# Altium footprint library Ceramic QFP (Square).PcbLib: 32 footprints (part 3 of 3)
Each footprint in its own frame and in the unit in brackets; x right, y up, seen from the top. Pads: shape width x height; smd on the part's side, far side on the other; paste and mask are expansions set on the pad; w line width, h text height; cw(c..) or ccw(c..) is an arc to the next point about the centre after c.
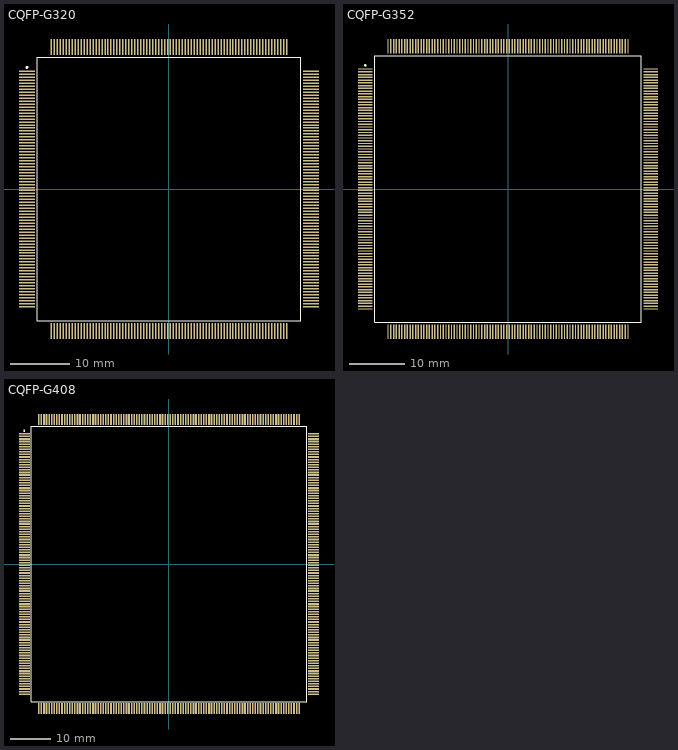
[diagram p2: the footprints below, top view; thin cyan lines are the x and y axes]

## CQFP-G320 [mm]
pads (320):
  rect 2.65x0.25 smd: 1(-23.875,19.75) 2(-23.875,19.25) 3(-23.875,18.75) 4(-23.875,18.25) 5(-23.875,17.75) 6(-23.875,17.25) 7(-23.875,16.75) 8(-23.875,16.25) 9(-23.875,15.75) 10(-23.875,15.25) 11(-23.875,14.75) 12(-23.875,14.25) 13(-23.875,13.75) 14(-23.875,13.25) 15(-23.875,12.75) 16(-23.875,12.25) 17(-23.875,11.75) 18(-23.875,11.25) 19(-23.875,10.75) 20(-23.875,10.25) 21(-23.875,9.75) 22(-23.875,9.25) 23(-23.875,8.75) 24(-23.875,8.25) 25(-23.875,7.75) 26(-23.875,7.25) 27(-23.875,6.75) 28(-23.875,6.25) 29(-23.875,5.75) 30(-23.875,5.25) 31(-23.875,4.75) 32(-23.875,4.25) 33(-23.875,3.75) 34(-23.875,3.25) 35(-23.875,2.75) 36(-23.875,2.25) 37(-23.875,1.75) 38(-23.875,1.25) 39(-23.875,0.75) 40(-23.875,0.25) 41(-23.875,-0.25) 42(-23.875,-0.75) 43(-23.875,-1.25) 44(-23.875,-1.75) 45(-23.875,-2.25) 46(-23.875,-2.75) 47(-23.875,-3.25) 48(-23.875,-3.75) 49(-23.875,-4.25) 50(-23.875,-4.75) 51(-23.875,-5.25) 52(-23.875,-5.75) 53(-23.875,-6.25) 54(-23.875,-6.75) 55(-23.875,-7.25) 56(-23.875,-7.75) 57(-23.875,-8.25) 58(-23.875,-8.75) 59(-23.875,-9.25) 60(-23.875,-9.75) 61(-23.875,-10.25) 62(-23.875,-10.75) 63(-23.875,-11.25) 64(-23.875,-11.75) 65(-23.875,-12.25) 66(-23.875,-12.75) 67(-23.875,-13.25) 68(-23.875,-13.75) 69(-23.875,-14.25) 70(-23.875,-14.75) 71(-23.875,-15.25) 72(-23.875,-15.75) 73(-23.875,-16.25) 74(-23.875,-16.75) 75(-23.875,-17.25) 76(-23.875,-17.75) 77(-23.875,-18.25) 78(-23.875,-18.75) 79(-23.875,-19.25) 80(-23.875,-19.75) 161(23.875,-19.75) 162(23.875,-19.25) 163(23.875,-18.75) 164(23.875,-18.25) 165(23.875,-17.75) 166(23.875,-17.25) 167(23.875,-16.75) 168(23.875,-16.25) 169(23.875,-15.75) 170(23.875,-15.25) 171(23.875,-14.75) 172(23.875,-14.25) 173(23.875,-13.75) 174(23.875,-13.25) 175(23.875,-12.75) 176(23.875,-12.25) 177(23.875,-11.75) 178(23.875,-11.25) 179(23.875,-10.75) 180(23.875,-10.25) 181(23.875,-9.75) 182(23.875,-9.25) 183(23.875,-8.75) 184(23.875,-8.25) 185(23.875,-7.75) 186(23.875,-7.25) 187(23.875,-6.75) 188(23.875,-6.25) 189(23.875,-5.75) 190(23.875,-5.25) 191(23.875,-4.75) 192(23.875,-4.25) 193(23.875,-3.75) 194(23.875,-3.25) 195(23.875,-2.75) 196(23.875,-2.25) 197(23.875,-1.75) 198(23.875,-1.25) 199(23.875,-0.75) 200(23.875,-0.25) 201(23.875,0.25) 202(23.875,0.75) 203(23.875,1.25) 204(23.875,1.75) 205(23.875,2.25) 206(23.875,2.75) 207(23.875,3.25) 208(23.875,3.75) 209(23.875,4.25) 210(23.875,4.75) 211(23.875,5.25) 212(23.875,5.75) 213(23.875,6.25) 214(23.875,6.75) 215(23.875,7.25) 216(23.875,7.75) 217(23.875,8.25) 218(23.875,8.75) 219(23.875,9.25) 220(23.875,9.75) 221(23.875,10.25) 222(23.875,10.75) 223(23.875,11.25) 224(23.875,11.75) 225(23.875,12.25) 226(23.875,12.75) 227(23.875,13.25) 228(23.875,13.75) 229(23.875,14.25) 230(23.875,14.75) 231(23.875,15.25) 232(23.875,15.75) 233(23.875,16.25) 234(23.875,16.75) 235(23.875,17.25) 236(23.875,17.75) 237(23.875,18.25) 238(23.875,18.75) 239(23.875,19.25) 240(23.875,19.75)
  rect 0.25x2.65 smd: 81(-19.75,-23.875) 82(-19.25,-23.875) 83(-18.75,-23.875) 84(-18.25,-23.875) 85(-17.75,-23.875) 86(-17.25,-23.875) 87(-16.75,-23.875) 88(-16.25,-23.875) 89(-15.75,-23.875) 90(-15.25,-23.875) 91(-14.75,-23.875) 92(-14.25,-23.875) 93(-13.75,-23.875) 94(-13.25,-23.875) 95(-12.75,-23.875) 96(-12.25,-23.875) 97(-11.75,-23.875) 98(-11.25,-23.875) 99(-10.75,-23.875) 100(-10.25,-23.875) 101(-9.75,-23.875) 102(-9.25,-23.875) 103(-8.75,-23.875) 104(-8.25,-23.875) 105(-7.75,-23.875) 106(-7.25,-23.875) 107(-6.75,-23.875) 108(-6.25,-23.875) 109(-5.75,-23.875) 110(-5.25,-23.875) 111(-4.75,-23.875) 112(-4.25,-23.875) 113(-3.75,-23.875) 114(-3.25,-23.875) 115(-2.75,-23.875) 116(-2.25,-23.875) 117(-1.75,-23.875) 118(-1.25,-23.875) 119(-0.75,-23.875) 120(-0.25,-23.875) 121(0.25,-23.875) 122(0.75,-23.875) 123(1.25,-23.875) 124(1.75,-23.875) 125(2.25,-23.875) 126(2.75,-23.875) 127(3.25,-23.875) 128(3.75,-23.875) 129(4.25,-23.875) 130(4.75,-23.875) 131(5.25,-23.875) 132(5.75,-23.875) 133(6.25,-23.875) 134(6.75,-23.875) 135(7.25,-23.875) 136(7.75,-23.875) 137(8.25,-23.875) 138(8.75,-23.875) 139(9.25,-23.875) 140(9.75,-23.875) 141(10.25,-23.875) 142(10.75,-23.875) 143(11.25,-23.875) 144(11.75,-23.875) 145(12.25,-23.875) 146(12.75,-23.875) 147(13.25,-23.875) 148(13.75,-23.875) 149(14.25,-23.875) 150(14.75,-23.875) 151(15.25,-23.875) 152(15.75,-23.875) 153(16.25,-23.875) 154(16.75,-23.875) 155(17.25,-23.875) 156(17.75,-23.875) 157(18.25,-23.875) 158(18.75,-23.875) 159(19.25,-23.875) 160(19.75,-23.875) 241(19.75,23.875) 242(19.25,23.875) 243(18.75,23.875) 244(18.25,23.875) 245(17.75,23.875) 246(17.25,23.875) 247(16.75,23.875) 248(16.25,23.875) 249(15.75,23.875) 250(15.25,23.875) 251(14.75,23.875) 252(14.25,23.875) 253(13.75,23.875) 254(13.25,23.875) 255(12.75,23.875) 256(12.25,23.875) 257(11.75,23.875) 258(11.25,23.875) 259(10.75,23.875) 260(10.25,23.875) 261(9.75,23.875) 262(9.25,23.875) 263(8.75,23.875) 264(8.25,23.875) 265(7.75,23.875) 266(7.25,23.875) 267(6.75,23.875) 268(6.25,23.875) 269(5.75,23.875) 270(5.25,23.875) 271(4.75,23.875) 272(4.25,23.875) 273(3.75,23.875) 274(3.25,23.875) 275(2.75,23.875) 276(2.25,23.875) 277(1.75,23.875) 278(1.25,23.875) 279(0.75,23.875) 280(0.25,23.875) 281(-0.25,23.875) 282(-0.75,23.875) 283(-1.25,23.875) 284(-1.75,23.875) 285(-2.25,23.875) 286(-2.75,23.875) 287(-3.25,23.875) 288(-3.75,23.875) 289(-4.25,23.875) 290(-4.75,23.875) 291(-5.25,23.875) 292(-5.75,23.875) 293(-6.25,23.875) 294(-6.75,23.875) 295(-7.25,23.875) 296(-7.75,23.875) 297(-8.25,23.875) 298(-8.75,23.875) 299(-9.25,23.875) 300(-9.75,23.875) 301(-10.25,23.875) 302(-10.75,23.875) 303(-11.25,23.875) 304(-11.75,23.875) 305(-12.25,23.875) 306(-12.75,23.875) 307(-13.25,23.875) 308(-13.75,23.875) 309(-14.25,23.875) 310(-14.75,23.875) 311(-15.25,23.875) 312(-15.75,23.875) 313(-16.25,23.875) 314(-16.75,23.875) 315(-17.25,23.875) 316(-17.75,23.875) 317(-18.25,23.875) 318(-18.75,23.875) 319(-19.25,23.875) 320(-19.75,23.875)
Top Overlay:
  circle w0.25: c-23.875,20.425 r0.125
  lines w0.2: -22.15,-22.15 -22.15,22.15 22.15,22.15 22.15,-22.15 -22.15,-22.15

## CQFP-G352 [mm]
pads (352):
  rect 2.65x0.25 smd: 1(-25.875,21.75) 2(-25.875,21.25) 3(-25.875,20.75) 4(-25.875,20.25) 5(-25.875,19.75) 6(-25.875,19.25) 7(-25.875,18.75) 8(-25.875,18.25) 9(-25.875,17.75) 10(-25.875,17.25) 11(-25.875,16.75) 12(-25.875,16.25) 13(-25.875,15.75) 14(-25.875,15.25) 15(-25.875,14.75) 16(-25.875,14.25) 17(-25.875,13.75) 18(-25.875,13.25) 19(-25.875,12.75) 20(-25.875,12.25) 21(-25.875,11.75) 22(-25.875,11.25) 23(-25.875,10.75) 24(-25.875,10.25) 25(-25.875,9.75) 26(-25.875,9.25) 27(-25.875,8.75) 28(-25.875,8.25) 29(-25.875,7.75) 30(-25.875,7.25) 31(-25.875,6.75) 32(-25.875,6.25) 33(-25.875,5.75) 34(-25.875,5.25) 35(-25.875,4.75) 36(-25.875,4.25) 37(-25.875,3.75) 38(-25.875,3.25) 39(-25.875,2.75) 40(-25.875,2.25) 41(-25.875,1.75) 42(-25.875,1.25) 43(-25.875,0.75) 44(-25.875,0.25) 45(-25.875,-0.25) 46(-25.875,-0.75) 47(-25.875,-1.25) 48(-25.875,-1.75) 49(-25.875,-2.25) 50(-25.875,-2.75) 51(-25.875,-3.25) 52(-25.875,-3.75) 53(-25.875,-4.25) 54(-25.875,-4.75) 55(-25.875,-5.25) 56(-25.875,-5.75) 57(-25.875,-6.25) 58(-25.875,-6.75) 59(-25.875,-7.25) 60(-25.875,-7.75) 61(-25.875,-8.25) 62(-25.875,-8.75) 63(-25.875,-9.25) 64(-25.875,-9.75) 65(-25.875,-10.25) 66(-25.875,-10.75) 67(-25.875,-11.25) 68(-25.875,-11.75) 69(-25.875,-12.25) 70(-25.875,-12.75) 71(-25.875,-13.25) 72(-25.875,-13.75) 73(-25.875,-14.25) 74(-25.875,-14.75) 75(-25.875,-15.25) 76(-25.875,-15.75) 77(-25.875,-16.25) 78(-25.875,-16.75) 79(-25.875,-17.25) 80(-25.875,-17.75) 81(-25.875,-18.25) 82(-25.875,-18.75) 83(-25.875,-19.25) 84(-25.875,-19.75) 85(-25.875,-20.25) 86(-25.875,-20.75) 87(-25.875,-21.25) 88(-25.875,-21.75) 177(25.875,-21.75) 178(25.875,-21.25) 179(25.875,-20.75) 180(25.875,-20.25) 181(25.875,-19.75) 182(25.875,-19.25) 183(25.875,-18.75) 184(25.875,-18.25) 185(25.875,-17.75) 186(25.875,-17.25) 187(25.875,-16.75) 188(25.875,-16.25) 189(25.875,-15.75) 190(25.875,-15.25) 191(25.875,-14.75) 192(25.875,-14.25) 193(25.875,-13.75) 194(25.875,-13.25) 195(25.875,-12.75) 196(25.875,-12.25) 197(25.875,-11.75) 198(25.875,-11.25) 199(25.875,-10.75) 200(25.875,-10.25) 201(25.875,-9.75) 202(25.875,-9.25) 203(25.875,-8.75) 204(25.875,-8.25) 205(25.875,-7.75) 206(25.875,-7.25) 207(25.875,-6.75) 208(25.875,-6.25) 209(25.875,-5.75) 210(25.875,-5.25) 211(25.875,-4.75) 212(25.875,-4.25) 213(25.875,-3.75) 214(25.875,-3.25) 215(25.875,-2.75) 216(25.875,-2.25) 217(25.875,-1.75) 218(25.875,-1.25) 219(25.875,-0.75) 220(25.875,-0.25) 221(25.875,0.25) 222(25.875,0.75) 223(25.875,1.25) 224(25.875,1.75) 225(25.875,2.25) 226(25.875,2.75) 227(25.875,3.25) 228(25.875,3.75) 229(25.875,4.25) 230(25.875,4.75) 231(25.875,5.25) 232(25.875,5.75) 233(25.875,6.25) 234(25.875,6.75) 235(25.875,7.25) 236(25.875,7.75) 237(25.875,8.25) 238(25.875,8.75) 239(25.875,9.25) 240(25.875,9.75) 241(25.875,10.25) 242(25.875,10.75) 243(25.875,11.25) 244(25.875,11.75) 245(25.875,12.25) 246(25.875,12.75) 247(25.875,13.25) 248(25.875,13.75) 249(25.875,14.25) 250(25.875,14.75) 251(25.875,15.25) 252(25.875,15.75) 253(25.875,16.25) 254(25.875,16.75) 255(25.875,17.25) 256(25.875,17.75) 257(25.875,18.25) 258(25.875,18.75) 259(25.875,19.25) 260(25.875,19.75) 261(25.875,20.25) 262(25.875,20.75) 263(25.875,21.25) 264(25.875,21.75)
  rect 0.25x2.65 smd: 89(-21.75,-25.875) 90(-21.25,-25.875) 91(-20.75,-25.875) 92(-20.25,-25.875) 93(-19.75,-25.875) 94(-19.25,-25.875) 95(-18.75,-25.875) 96(-18.25,-25.875) 97(-17.75,-25.875) 98(-17.25,-25.875) 99(-16.75,-25.875) 100(-16.25,-25.875) 101(-15.75,-25.875) 102(-15.25,-25.875) 103(-14.75,-25.875) 104(-14.25,-25.875) 105(-13.75,-25.875) 106(-13.25,-25.875) 107(-12.75,-25.875) 108(-12.25,-25.875) 109(-11.75,-25.875) 110(-11.25,-25.875) 111(-10.75,-25.875) 112(-10.25,-25.875) 113(-9.75,-25.875) 114(-9.25,-25.875) 115(-8.75,-25.875) 116(-8.25,-25.875) 117(-7.75,-25.875) 118(-7.25,-25.875) 119(-6.75,-25.875) 120(-6.25,-25.875) 121(-5.75,-25.875) 122(-5.25,-25.875) 123(-4.75,-25.875) 124(-4.25,-25.875) 125(-3.75,-25.875) 126(-3.25,-25.875) 127(-2.75,-25.875) 128(-2.25,-25.875) 129(-1.75,-25.875) 130(-1.25,-25.875) 131(-0.75,-25.875) 132(-0.25,-25.875) 133(0.25,-25.875) 134(0.75,-25.875) 135(1.25,-25.875) 136(1.75,-25.875) 137(2.25,-25.875) 138(2.75,-25.875) 139(3.25,-25.875) 140(3.75,-25.875) 141(4.25,-25.875) 142(4.75,-25.875) 143(5.25,-25.875) 144(5.75,-25.875) 145(6.25,-25.875) 146(6.75,-25.875) 147(7.25,-25.875) 148(7.75,-25.875) 149(8.25,-25.875) 150(8.75,-25.875) 151(9.25,-25.875) 152(9.75,-25.875) 153(10.25,-25.875) 154(10.75,-25.875) 155(11.25,-25.875) 156(11.75,-25.875) 157(12.25,-25.875) 158(12.75,-25.875) 159(13.25,-25.875) 160(13.75,-25.875) 161(14.25,-25.875) 162(14.75,-25.875) 163(15.25,-25.875) 164(15.75,-25.875) 165(16.25,-25.875) 166(16.75,-25.875) 167(17.25,-25.875) 168(17.75,-25.875) 169(18.25,-25.875) 170(18.75,-25.875) 171(19.25,-25.875) 172(19.75,-25.875) 173(20.25,-25.875) 174(20.75,-25.875) 175(21.25,-25.875) 176(21.75,-25.875) 265(21.75,25.875) 266(21.25,25.875) 267(20.75,25.875) 268(20.25,25.875) 269(19.75,25.875) 270(19.25,25.875) 271(18.75,25.875) 272(18.25,25.875) 273(17.75,25.875) 274(17.25,25.875) 275(16.75,25.875) 276(16.25,25.875) 277(15.75,25.875) 278(15.25,25.875) 279(14.75,25.875) 280(14.25,25.875) 281(13.75,25.875) 282(13.25,25.875) 283(12.75,25.875) 284(12.25,25.875) 285(11.75,25.875) 286(11.25,25.875) 287(10.75,25.875) 288(10.25,25.875) 289(9.75,25.875) 290(9.25,25.875) 291(8.75,25.875) 292(8.25,25.875) 293(7.75,25.875) 294(7.25,25.875) 295(6.75,25.875) 296(6.25,25.875) 297(5.75,25.875) 298(5.25,25.875) 299(4.75,25.875) 300(4.25,25.875) 301(3.75,25.875) 302(3.25,25.875) 303(2.75,25.875) 304(2.25,25.875) 305(1.75,25.875) 306(1.25,25.875) 307(0.75,25.875) 308(0.25,25.875) 309(-0.25,25.875) 310(-0.75,25.875) 311(-1.25,25.875) 312(-1.75,25.875) 313(-2.25,25.875) 314(-2.75,25.875) 315(-3.25,25.875) 316(-3.75,25.875) 317(-4.25,25.875) 318(-4.75,25.875) 319(-5.25,25.875) 320(-5.75,25.875) 321(-6.25,25.875) 322(-6.75,25.875) 323(-7.25,25.875) 324(-7.75,25.875) 325(-8.25,25.875) 326(-8.75,25.875) 327(-9.25,25.875) 328(-9.75,25.875) 329(-10.25,25.875) 330(-10.75,25.875) 331(-11.25,25.875) 332(-11.75,25.875) 333(-12.25,25.875) 334(-12.75,25.875) 335(-13.25,25.875) 336(-13.75,25.875) 337(-14.25,25.875) 338(-14.75,25.875) 339(-15.25,25.875) 340(-15.75,25.875) 341(-16.25,25.875) 342(-16.75,25.875) 343(-17.25,25.875) 344(-17.75,25.875) 345(-18.25,25.875) 346(-18.75,25.875) 347(-19.25,25.875) 348(-19.75,25.875) 349(-20.25,25.875) 350(-20.75,25.875) 351(-21.25,25.875) 352(-21.75,25.875)
Top Overlay:
  circle w0.25: c-25.875,22.425 r0.125
  lines w0.2: -24.15,-24.15 -24.15,24.15 24.15,24.15 24.15,-24.15 -24.15,-24.15

## CQFP-G408 [mm]
pads (408):
  rect 2.65x0.4 smd: 1(-35.625,32.07) 2(-35.625,31.435) 3(-35.625,30.8) 4(-35.625,30.165) 5(-35.625,29.53) 6(-35.625,28.895) 7(-35.625,28.26) 8(-35.625,27.625) 9(-35.625,26.99) 10(-35.625,26.355) 11(-35.625,25.72) 12(-35.625,25.085) 13(-35.625,24.45) 14(-35.625,23.815) 15(-35.625,23.18) 16(-35.625,22.545) 17(-35.625,21.91) 18(-35.625,21.275) 19(-35.625,20.64) 20(-35.625,20.005) 21(-35.625,19.37) 22(-35.625,18.735) 23(-35.625,18.1) 24(-35.625,17.465) 25(-35.625,16.83) 26(-35.625,16.195) 27(-35.625,15.56) 28(-35.625,14.925) 29(-35.625,14.29) 30(-35.625,13.655) 31(-35.625,13.02) 32(-35.625,12.385) 33(-35.625,11.75) 34(-35.625,11.115) 35(-35.625,10.48) 36(-35.625,9.845) 37(-35.625,9.21) 38(-35.625,8.575) 39(-35.625,7.94) 40(-35.625,7.305) 41(-35.625,6.67) 42(-35.625,6.035) 43(-35.625,5.4) 44(-35.625,4.765) 45(-35.625,4.13) 46(-35.625,3.495) 47(-35.625,2.86) 48(-35.625,2.225) 49(-35.625,1.59) 50(-35.625,0.955) 51(-35.625,0.32) 52(-35.625,-0.315) 53(-35.625,-0.95) 54(-35.625,-1.585) 55(-35.625,-2.22) 56(-35.625,-2.855) 57(-35.625,-3.49) 58(-35.625,-4.125) 59(-35.625,-4.76) 60(-35.625,-5.395) 61(-35.625,-6.03) 62(-35.625,-6.665) 63(-35.625,-7.3) 64(-35.625,-7.935) 65(-35.625,-8.57) 66(-35.625,-9.205) 67(-35.625,-9.84) 68(-35.625,-10.475) 69(-35.625,-11.11) 70(-35.625,-11.745) 71(-35.625,-12.38) 72(-35.625,-13.015) 73(-35.625,-13.65) 74(-35.625,-14.285) 75(-35.625,-14.92) 76(-35.625,-15.555) 77(-35.625,-16.19) 78(-35.625,-16.825) 79(-35.625,-17.46) 80(-35.625,-18.095) 81(-35.625,-18.73) 82(-35.625,-19.365) 83(-35.625,-20) 84(-35.625,-20.635) 85(-35.625,-21.27) 86(-35.625,-21.905) 87(-35.625,-22.54) 88(-35.625,-23.175) 89(-35.625,-23.81) 90(-35.625,-24.445) 91(-35.625,-25.08) 92(-35.625,-25.715) 93(-35.625,-26.35) 94(-35.625,-26.985) 95(-35.625,-27.62) 96(-35.625,-28.255) 97(-35.625,-28.89) 98(-35.625,-29.525) 99(-35.625,-30.16) 100(-35.625,-30.795) 101(-35.625,-31.43) 102(-35.625,-32.065) 205(35.625,-32.065) 206(35.625,-31.43) 207(35.625,-30.795) 208(35.625,-30.16) 209(35.625,-29.525) 210(35.625,-28.89) 211(35.625,-28.255) 212(35.625,-27.62) 213(35.625,-26.985) 214(35.625,-26.35) 215(35.625,-25.715) 216(35.625,-25.08) 217(35.625,-24.445) 218(35.625,-23.81) 219(35.625,-23.175) 220(35.625,-22.54) 221(35.625,-21.905) 222(35.625,-21.27) 223(35.625,-20.635) 224(35.625,-20) 225(35.625,-19.365) 226(35.625,-18.73) 227(35.625,-18.095) 228(35.625,-17.46) 229(35.625,-16.825) 230(35.625,-16.19) 231(35.625,-15.555) 232(35.625,-14.92) 233(35.625,-14.285) 234(35.625,-13.65) 235(35.625,-13.015) 236(35.625,-12.38) 237(35.625,-11.745) 238(35.625,-11.11) 239(35.625,-10.475) 240(35.625,-9.84) 241(35.625,-9.205) 242(35.625,-8.57) 243(35.625,-7.935) 244(35.625,-7.3) 245(35.625,-6.665) 246(35.625,-6.03) 247(35.625,-5.395) 248(35.625,-4.76) 249(35.625,-4.125) 250(35.625,-3.49) 251(35.625,-2.855) 252(35.625,-2.22) 253(35.625,-1.585) 254(35.625,-0.95) 255(35.625,-0.315) 256(35.625,0.32) 257(35.625,0.955) 258(35.625,1.59) 259(35.625,2.225) 260(35.625,2.86) 261(35.625,3.495) 262(35.625,4.13) 263(35.625,4.765) 264(35.625,5.4) 265(35.625,6.035) 266(35.625,6.67) 267(35.625,7.305) 268(35.625,7.94) 269(35.625,8.575) 270(35.625,9.21) 271(35.625,9.845) 272(35.625,10.48) 273(35.625,11.115) 274(35.625,11.75) 275(35.625,12.385) 276(35.625,13.02) 277(35.625,13.655) 278(35.625,14.29) 279(35.625,14.925) 280(35.625,15.56) 281(35.625,16.195) 282(35.625,16.83) 283(35.625,17.465) 284(35.625,18.1) 285(35.625,18.735) 286(35.625,19.37) 287(35.625,20.005) 288(35.625,20.64) 289(35.625,21.275) 290(35.625,21.91) 291(35.625,22.545) 292(35.625,23.18) 293(35.625,23.815) 294(35.625,24.45) 295(35.625,25.085) 296(35.625,25.72) 297(35.625,26.355) 298(35.625,26.99) 299(35.625,27.625) 300(35.625,28.26) 301(35.625,28.895) 302(35.625,29.53) 303(35.625,30.165) 304(35.625,30.8) 305(35.625,31.435) 306(35.625,32.07)
  rect 0.4x2.65 smd: 103(-32.07,-35.625) 104(-31.435,-35.625) 105(-30.8,-35.625) 106(-30.165,-35.625) 107(-29.53,-35.625) 108(-28.895,-35.625) 109(-28.26,-35.625) 110(-27.625,-35.625) 111(-26.99,-35.625) 112(-26.355,-35.625) 113(-25.72,-35.625) 114(-25.085,-35.625) 115(-24.45,-35.625) 116(-23.815,-35.625) 117(-23.18,-35.625) 118(-22.545,-35.625) 119(-21.91,-35.625) 120(-21.275,-35.625) 121(-20.64,-35.625) 122(-20.005,-35.625) 123(-19.37,-35.625) 124(-18.735,-35.625) 125(-18.1,-35.625) 126(-17.465,-35.625) 127(-16.83,-35.625) 128(-16.195,-35.625) 129(-15.56,-35.625) 130(-14.925,-35.625) 131(-14.29,-35.625) 132(-13.655,-35.625) 133(-13.02,-35.625) 134(-12.385,-35.625) 135(-11.75,-35.625) 136(-11.115,-35.625) 137(-10.48,-35.625) 138(-9.845,-35.625) 139(-9.21,-35.625) 140(-8.575,-35.625) 141(-7.94,-35.625) 142(-7.305,-35.625) 143(-6.67,-35.625) 144(-6.035,-35.625) 145(-5.4,-35.625) 146(-4.765,-35.625) 147(-4.13,-35.625) 148(-3.495,-35.625) 149(-2.86,-35.625) 150(-2.225,-35.625) 151(-1.59,-35.625) 152(-0.955,-35.625) 153(-0.32,-35.625) 154(0.315,-35.625) 155(0.95,-35.625) 156(1.585,-35.625) 157(2.22,-35.625) 158(2.855,-35.625) 159(3.49,-35.625) 160(4.125,-35.625) 161(4.76,-35.625) 162(5.395,-35.625) 163(6.03,-35.625) 164(6.665,-35.625) 165(7.3,-35.625) 166(7.935,-35.625) 167(8.57,-35.625) 168(9.205,-35.625) 169(9.84,-35.625) 170(10.475,-35.625) 171(11.11,-35.625) 172(11.745,-35.625) 173(12.38,-35.625) 174(13.015,-35.625) 175(13.65,-35.625) 176(14.285,-35.625) 177(14.92,-35.625) 178(15.555,-35.625) 179(16.19,-35.625) 180(16.825,-35.625) 181(17.46,-35.625) 182(18.095,-35.625) 183(18.73,-35.625) 184(19.365,-35.625) 185(20,-35.625) 186(20.635,-35.625) 187(21.27,-35.625) 188(21.905,-35.625) 189(22.54,-35.625) 190(23.175,-35.625) 191(23.81,-35.625) 192(24.445,-35.625) 193(25.08,-35.625) 194(25.715,-35.625) 195(26.35,-35.625) 196(26.985,-35.625) 197(27.62,-35.625) 198(28.255,-35.625) 199(28.89,-35.625) 200(29.525,-35.625) 201(30.16,-35.625) 202(30.795,-35.625) 203(31.43,-35.625) 204(32.065,-35.625) 307(32.065,35.625) 308(31.43,35.625) 309(30.795,35.625) 310(30.16,35.625) 311(29.525,35.625) 312(28.89,35.625) 313(28.255,35.625) 314(27.62,35.625) 315(26.985,35.625) 316(26.35,35.625) 317(25.715,35.625) 318(25.08,35.625) 319(24.445,35.625) 320(23.81,35.625) 321(23.175,35.625) 322(22.54,35.625) 323(21.905,35.625) 324(21.27,35.625) 325(20.635,35.625) 326(20,35.625) 327(19.365,35.625) 328(18.73,35.625) 329(18.095,35.625) 330(17.46,35.625) 331(16.825,35.625) 332(16.19,35.625) 333(15.555,35.625) 334(14.92,35.625) 335(14.285,35.625) 336(13.65,35.625) 337(13.015,35.625) 338(12.38,35.625) 339(11.745,35.625) 340(11.11,35.625) 341(10.475,35.625) 342(9.84,35.625) 343(9.205,35.625) 344(8.57,35.625) 345(7.935,35.625) 346(7.3,35.625) 347(6.665,35.625) 348(6.03,35.625) 349(5.395,35.625) 350(4.76,35.625) 351(4.125,35.625) 352(3.49,35.625) 353(2.855,35.625) 354(2.22,35.625) 355(1.585,35.625) 356(0.95,35.625) 357(0.315,35.625) 358(-0.32,35.625) 359(-0.955,35.625) 360(-1.59,35.625) 361(-2.225,35.625) 362(-2.86,35.625) 363(-3.495,35.625) 364(-4.13,35.625) 365(-4.765,35.625) 366(-5.4,35.625) 367(-6.035,35.625) 368(-6.67,35.625) 369(-7.305,35.625) 370(-7.94,35.625) 371(-8.575,35.625) 372(-9.21,35.625) 373(-9.845,35.625) 374(-10.48,35.625) 375(-11.115,35.625) 376(-11.75,35.625) 377(-12.385,35.625) 378(-13.02,35.625) 379(-13.655,35.625) 380(-14.29,35.625) 381(-14.925,35.625) 382(-15.56,35.625) 383(-16.195,35.625) 384(-16.83,35.625) 385(-17.465,35.625) 386(-18.1,35.625) 387(-18.735,35.625) 388(-19.37,35.625) 389(-20.005,35.625) 390(-20.64,35.625) 391(-21.275,35.625) 392(-21.91,35.625) 393(-22.545,35.625) 394(-23.18,35.625) 395(-23.815,35.625) 396(-24.45,35.625) 397(-25.085,35.625) 398(-25.72,35.625) 399(-26.355,35.625) 400(-26.99,35.625) 401(-27.625,35.625) 402(-28.26,35.625) 403(-28.895,35.625) 404(-29.53,35.625) 405(-30.165,35.625) 406(-30.8,35.625) 407(-31.435,35.625) 408(-32.07,35.625)
Top Overlay:
  circle w0.25: c-35.625,32.82 r0.125
  lines w0.2: -33.9,-33.9 -33.9,33.9 33.9,33.9 33.9,-33.9 -33.9,-33.9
